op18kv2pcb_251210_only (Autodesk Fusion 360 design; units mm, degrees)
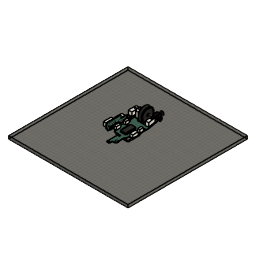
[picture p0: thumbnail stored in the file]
parameter "d441" = 0.2
place_component sketch "スケッチ1"
sketch "スケッチ1" plane through (0, 0, 0) normal (0, 0, 1) x axis (1, 0, 0)
  line L1 (-100, -100) -> (100, -100)
  line L2 (-100, 100) -> (-100, -100)
  line L3 (100, 100) -> (-100, 100)
  line L4 (100, -100) -> (100, 100)
  line L5 (-100, 100) -> (100, -100)
  line L6 (100, 100) -> (-100, -100)
  point P6 (0, 0)
  point P1 (0, 0)
  point P4 (-100, 100)
  point P5 (100, 100)
  point P3 (-100, -100)
  horizontal L1
  perpendicular L1 L2
  parallel L1 L3
  parallel L2 L4
  coincident L5 P6
  coincident L6 P6
  coincident P1 P6
  dimension "d13" distance P4 P5 = 200
  dimension "d14" distance P3 P4 = 200
extrude "押し出し1" new body sketch "スケッチ1" profile of L1 L2 L3 L4 against normal blind 5
sketch "スケッチ1" plane through (0, 0, 0) normal (0, 0, 1) x axis (1, 0, 0)
  line L1 (2, 0) -> (-2, 0)
  line L2 (2, -4) -> (2, 0)
  line L3 (-2, -4) -> (2, -4)
  line L4 (-2, 0) -> (-2, -4)
  line L5 (0, -7.68) -> (0, 0)
  line L6 (4.05, 8.27) -> (-4.05, 8.27)
  line L7 (4.05, -7.68) -> (4.05, 8.27)
  line L8 (-4.05, -7.68) -> (4.05, -7.68)
  line L9 (-4.05, 8.27) -> (-4.05, -7.68)
  arc A1 centre (0, 0) radius 2 clockwise from (-2, 0) to (2, 0)
  point P7 (0, -7.68)
  point P6 (0, 0)
  point P12 (0, 0)
  point P2 (-2, 0)
  point P3 (2, 0)
  point P5 (-2, -4)
  point P8 (-4.05, 8.27)
  point P9 (4.05, 8.27)
  point P11 (-4.05, -7.68)
  horizontal L1
  vertical L2
  horizontal L3
  vertical L4
  perpendicular L3 L5
  horizontal L6
  vertical L7
  horizontal L8
  vertical L9
  midpoint P7 L8
  coincident P6 P12
  dimension "d2" distance P2 P3 = 4
  dimension "d3" distance P2 P5 = 4
  dimension "d4" distance P6 P7 = 7.68
  dimension "d5" distance P8 P9 = 8.1
  dimension "d6" distance P8 P11 = 15.95
  dimension "d21" radius A1 = 2
extrude "押し出し2" new body sketch "スケッチ1" profile of L1 L2 L3 L4 L5 A1 along normal blind 2.4 taper 22.5 bodies "lens"
extrude "押し出し5" add sketch "スケッチ1" to an object from offset 7.4
sketch "スケッチ1" plane through (0, 0, 0) normal (0, 0, 1) x axis (1, 0, 0)
  line L1 (-10, -10) -> (10, -10)
  line L2 (-10, 10) -> (-10, -10)
  line L3 (10, 10) -> (-10, 10)
  line L4 (10, -10) -> (10, 10)
  line L5 (-10, 10) -> (10, -10)
  line L6 (10, 10) -> (-10, -10)
  line L7 (2, -4) -> (2, 0)
  line L8 (-2, -4) -> (2, -4)
  line L9 (-2, 0) -> (-2, -4)
  line L10 (3.5, -4.5) -> (3.5, 0)
  line L11 (-2.5, -5.5) -> (2.5, -5.5)
  line L12 (-3.5, 0) -> (-3.5, -4.5)
  line L13 (-6.5, 0) -> (-6.5, -4.5)
  line L14 (6.5, -4.5) -> (6.5, 0)
  line L15 (-2.5, -8.5) -> (2.5, -8.5)
  arc A1 centre (0, 0) radius 2 clockwise from (-2, 0) to (2, 0)
  arc A2 centre (0, 0) radius 3.5 clockwise from (-3.5, 0) to (3.5, 0)
  arc A3 centre (-2.5, -4.5) radius 1 clockwise from (-2.5, -5.5) to (-3.5, -4.5)
  arc A4 centre (2.5, -4.5) radius 1 clockwise from (3.5, -4.5) to (2.5, -5.5)
  arc A5 centre (0, 0) radius 6.5 clockwise from (-6.5, 0) to (6.5, 0)
  arc A6 centre (2.5, -4.5) radius 4 clockwise from (6.5, -4.5) to (2.5, -8.5)
  arc A7 centre (-2.5, -4.5) radius 4 clockwise from (-2.5, -8.5) to (-6.5, -4.5)
  point P6 (0, 0)
  point P1 (0, 0)
  point P7 (0, 0)
  point P4 (-10, 10)
  point P5 (10, 10)
  point P3 (-10, -10)
  point P9 (-2, 0)
  point P10 (2, 0)
  point P12 (-2, -4)
  horizontal L1
  perpendicular L1 L2
  parallel L1 L3
  parallel L2 L4
  coincident L5 P6
  coincident L6 P6
  coincident P1 P6
  coincident P1 P7
  vertical L7
  horizontal L8
  vertical L9
  concentric A1 A2
  tangent L12 A2
  tangent L12 A3
  tangent L11 A3
  tangent L10 A4
  tangent L11 A4
  equal A3 A4
  dimension "d29" distance P4 P5 = 20
  dimension "d30" distance P3 P4 = 20
  dimension "d40" radius A1 = 2
  dimension "d41" distance P9 P10 = 4
  dimension "d42" distance P9 P12 = 4
  dimension "d44" radius A3 = 1
  dimension "d45" = 3
extrude "押し出し2" sketch "スケッチ1" profile of L1 L2 L3 L4 A1 L7 L8 L9 L10 L11 L12 A2 A3 A4 L13 A7 L14 A5 A6 L15 to an object offset 0.5 from offset -0.5 bodies "around_lens"
extrude "押し出し3" cut sketch "スケッチ1" profile of L10 L11 L12 A2 A3 A4 L13 A7 L14 A5 A6 L15 along normal blind 0.7
combine "結合"
sketch "スケッチ1" plane through (0, 0, 0) normal (0, 0, 1) x axis (1, 0, 0)
  line L1 (0, -15) -> (0, 15)
  line L2 (-5.25, -15) -> (-5.25, 15)
  line L3 (5.25, -15) -> (5.25, 15)
  line L4 (-4.3, -15) -> (-4.3, 15)
  line L5 (4.3, -15) -> (4.3, 15)
  line L6 (10, 0) -> (-10, 0)
  line L7 (10, -8.44) -> (-10, -8.44)
  line L8 (10, 8.82) -> (-10, 8.82)
  line L9 (10, -5.66) -> (-10, -5.66)
  line L10 (10, 6.8) -> (-10, 6.8)
  line L11 (10, 7.69) -> (-10, 7.69)
  line L12 (10, -4.77) -> (-10, -4.77)
  line L13 (5.45, -15) -> (5.45, 15)
  line L14 (-5.45, -15) -> (-5.45, 15)
  line L15 (10, 7.94) -> (-10, 7.94)
  line L16 (10, 7.05) -> (-10, 7.05)
  line L17 (10, -5.02) -> (-10, -5.02)
  line L18 (10, -5.91) -> (-10, -5.91)
  point P1 (0, 0)
  vertical L1
  midpoint P1 L1
  perpendicular L2 L6
  midpoint P1 L6
  dimension "d91" = 5.25
  dimension "d92" = -5.25
  dimension "d93" = 4.3
  dimension "d94" = -4.3
  dimension "d95" = 8.44
  dimension "d96" = -8.82
  dimension "d97" = 5.66
  dimension "d102" = -12.46 (= "( -1.78 * 7 ) * 1 mm")
  dimension "d103" = -0.89
  dimension "d104" = -0.89
  dimension "d105" = -0.2
  dimension "d106" = 0.2
  dimension "d107" = -0.25
  dimension "d108" = -0.25
  dimension "d109" = 0.25
  dimension "d110" = 0.25
extrude "押し出し1" new body sketch "スケッチ1" profile of L1 L4 L5 L6 L7 L8 L9 L10 L11 L12 L15 L16 L17 L18 to an object offset 7.4 from offset 9.81 bodies "sensor"
extrude "押し出し2" sketch "スケッチ1" profile of L2 L3 L4 L5 L6 L9 L10 L11 L12 L13 L14 L15 L16 L17 L18 blind -0.2 from offset -0.5
extrude "押し出し3" sketch "スケッチ1" profile of L2 L3 L6 L9 L10 L11 L12 L13 L14 L15 L16 L17 L18 blind -4.51 from offset -0.5
sketch "スケッチ1" plane through (0, 0, 0) normal (0, 0, 1) x axis (1, 0, 0)
  line L1 (0, 15.4) -> (0, 0)
  line L2 (0, -14.4) -> (0, 0)
  line L3 (-4.3, 0) -> (4.3, 0)
  line L4 (-4.3, 8.82) -> (4.3, 8.82)
  line L5 (-4.3, -8.44) -> (4.3, -8.44)
  line L6 (4.3, 8.82) -> (4.3, -8.44)
  line L7 (-4.3, 8.82) -> (-4.3, -8.44)
  line L8 (12, 15.4) -> (0, 15.4)
  line L9 (-12.8, 15.4) -> (0, 15.4)
  line L10 (0, -31.8) -> (0, 0)
  circle C1 centre (12, 15.4) radius 1.4
  circle C2 centre (-12.8, 15.4) radius 1.4
  circle C3 centre (0, -14.4) radius 1.4
  circle C4 centre (0, -31.8) radius 1.4
  point P1 (0, 0)
  point P2 (0, 0)
  point P6 (0, 0)
  point P7 (0, -14.4)
  point P8 (0, -14.4)
  point P4 (12, 15.4)
  point P16 (12, 15.4)
  point P5 (-12.8, 15.4)
  point P17 (-12.8, 15.4)
  point P18 (0, 0)
  point P9 (0, -31.8)
  point P19 (0, -31.8)
  point P3 (0, 15.4)
  point P10 (4.3, 0)
  point P11 (-4.3, 0)
  coincident P1 P2
  vertical L1
  coincident P1 P6
  coincident P7 P8
  perpendicular L2 L3
  midpoint P6 L3
  perpendicular L4 L6
  perpendicular L4 L7
  perpendicular L1 L8
  perpendicular L1 L9
  coincident P4 P16
  coincident P5 P17
  coincident P1 P18
  perpendicular L3 L10
  coincident P9 P19
  dimension "d51" distance P2 P3 = 15.4
  dimension "d53" diameter C1 = 2.8
  dimension "d54" diameter C2 = 2.8
  dimension "d56" distance P6 P7 = 14.4
  dimension "d57" diameter C3 = 2.8
  dimension "d58" diameter C4 = 2.8
  dimension "d120" distance P10 P11 = 8.6
  dimension "d121" = 8.82
  dimension "d122" = -8.44
  dimension "d187" distance P3 P16 = 12
  dimension "d188" distance P3 P17 = 12.8
  dimension "d189" distance P18 P19 = 31.8
sketch "スケッチ2" plane through (0, 0, 0) normal (0, 0, 1) x axis (1, 0, 0)
  line L1 (50, 0) -> (-50, 0)
  line L2 (0, -50) -> (0, 50)
  line L3 (-13.8, -50) -> (-13.8, 50)
  line L4 (14, -50) -> (14, 50)
  line L5 (50, 39.3) -> (-50, 39.3)
  line L6 (50, -12.8) -> (-50, -12.8)
  line L7 (50, -33.6) -> (-50, -33.6)
  line L8 (-2.3, -50) -> (-2.3, 50)
  line L9 (2.3, -50) -> (2.3, 50)
  line L10 (7.3, -50) -> (7.3, 50)
  line L11 (50, -28.4) -> (-50, -28.4)
  line L12 (50, -9.7) -> (-50, -9.7)
  line L13 (-10.1, -50) -> (-10.1, 50)
  line L14 (9.3, -50) -> (9.3, 50)
  line L15 (50, -7.7) -> (-50, -7.7)
  line L16 (50, 36.5) -> (-50, 36.5)
  line L17 (-7.3, 39.3) -> (-10.1, 36.5)
  line L18 (10.6, -50) -> (10.6, 50)
  line L19 (14, 20.0176) -> (10.6, 39.3)
  point P1 (0, 0)
  point P34 (-10.1, 36.5)
  point P35 (-7.3, 39.3)
  point P38 (10.6, 39.3)
  point P39 (14, 20.0176)
  horizontal L1
  midpoint P1 L1
  vertical L2
  midpoint P1 L2
  coincident L13 P34
  coincident L16 P34
  coincident L5 P35
  coincident L18 P38
  coincident L5 P38
  coincident L4 P39
  dimension "d73" = 13.8
  dimension "d74" = -14
  dimension "d75" = -39.3
  dimension "d76" = 12.8
  dimension "d77" = 20.8
  dimension "d78" = 2.3
  dimension "d79" = -2.3
  dimension "d80" = -5
  dimension "d81" = -5.2
  dimension "d82" = -3.1
  dimension "d83" = -3.7
  dimension "d205" = 4.7
  dimension "d206" = -5.1
  dimension "d211" = -36.5
  dimension "d212" angle L5 L17 = 45
  dimension "d214" = 3.4
  dimension "d416" angle L5 L19 = 80
sketch "スケッチ3" plane through (0, 0, 0) normal (0, 0, 1) x axis (1, 0, 0)
  line L1 (25, 0) -> (-25, 0)
  line L2 (25, 22.2) -> (-25, 22.2)
  line L3 (25, 37.6) -> (-25, 37.6)
  line L4 (0, 50.6) -> (0, 0)
  line L5 (6.8, 50.6) -> (6.8, 0.6)
  line L6 (-6.8, 50.6) -> (-6.8, 0.6)
  line L7 (25, 36) -> (-25, 36)
  line L8 (25, 34.2) -> (-25, 34.2)
  line L9 (25, 23.1) -> (-25, 23.1)
  line L10 (25, 24.9) -> (-25, 24.9)
  line L11 (7.6, 50.6) -> (7.6, 0.6)
  line L12 (-7.6, 50.6) -> (-7.6, 0.6)
  circle C1 centre (-4.8, 35.6) radius 2
  circle C2 centre (-5.3, 23.7) radius 1.5
  circle C3 centre (5.6, 35.6) radius 2
  circle C4 centre (4.8, 24.2) radius 2
  point P1 (0, 0)
  point P8 (0, 0)
  horizontal L1
  coincident P1 P8
  perpendicular L3 L4
  tangent L6 C1
  tangent L3 C1
  tangent L2 C2
  tangent L6 C2
  tangent L3 C3
  tangent L11 C3
  tangent L5 C4
  tangent L2 C4
  dimension "d156" = -22.2
  dimension "d157" = -15.4
  dimension "d158" = 6.8
  dimension "d159" = -6.8
  dimension "d169" = 1.6
  dimension "d170" = 1.8
  dimension "d171" = -0.9
  dimension "d172" = -1.8
  dimension "d174" = 0.8
  dimension "d175" radius C1 = 2
  dimension "d176" radius C2 = 1.5
  dimension "d177" = -0.8
  dimension "d178" radius C3 = 2
  dimension "d179" radius C4 = 2
extrude "押し出し1" new body sketch "スケッチ2" blind -0.8 from offset 7.4 bodies "main_pcb"
extrude "押し出し2" cut sketch "スケッチ1" profile of L1 C1 C2 L2 C3 C4 L3 L4 L5 L6 L7 to an object
extrude "押し出し3" sketch "スケッチ3" profile of L2 L3 L4 L5 L6 L7 L8 L9 L10 L11 C1 C2 L12 C3 C4 to an object
sketch "スケッチ5" plane through (0, 0, 0) normal (0, 0, 1) x axis (1, 0, 0)
  line L1 (-12.25, 0) -> (0, 0)
  line L2 (-12.25, -5.5) -> (-12.25, 0)
  line L3 (0, -5.5) -> (-12.25, -5.5)
  line L4 (0, 0) -> (0, -5.5)
  line L5 (-11.45, 0) -> (0, 0)
  line L6 (-11.45, 9.05) -> (-11.45, 0)
  line L7 (0, 9.05) -> (-11.45, 9.05)
  line L8 (0, 0) -> (0, 9.05)
  line L9 (10.7, 0) -> (0, 0)
  line L10 (10.7, -2.8) -> (10.7, 0)
  line L11 (0, -2.8) -> (10.7, -2.8)
  line L12 (0, 0) -> (0, -2.8)
  line L13 (12.2, 0) -> (0, 0)
  line L14 (12.2, 9.05) -> (12.2, 0)
  line L15 (0, 9.05) -> (12.2, 9.05)
  line L16 (0, 0) -> (0, 9.05)
  line L17 (-12.5, -7.75) -> (-12.5, -3.25)
  line L18 (-12, -3.25) -> (-12, -7.75)
  line L19 (-12.25, -7.75) -> (-12.25, -3.25)
  line L20 (10.45, -5.8) -> (10.45, 0.2)
  line L21 (10.95, 0.2) -> (10.95, -5.8)
  line L22 (10.7, -5.8) -> (10.7, 0.2)
  line L23 (11.95, 7.55) -> (11.95, 10.55)
  line L24 (12.45, 10.55) -> (12.45, 7.55)
  line L25 (12.2, 7.55) -> (12.2, 10.55)
  line L26 (-11.7, 7.55) -> (-11.7, 10.55)
  line L27 (-11.2, 10.55) -> (-11.2, 7.55)
  line L28 (-11.45, 7.55) -> (-11.45, 10.55)
  line L29 (-13.8, -9.25) -> (-10.2, -9.25)
  line L30 (-13.8, -1.75) -> (-13.8, -9.25)
  line L31 (-10.2, -1.75) -> (-13.8, -1.75)
  line L32 (-10.2, -9.25) -> (-10.2, -1.75)
  line L33 (-13.8, -1.75) -> (-10.2, -9.25)
  line L34 (-10.2, -1.75) -> (-13.8, -9.25)
  line L35 (-13.5, 6.05) -> (-9.9, 6.05)
  line L36 (-13.5, 12.05) -> (-13.5, 6.05)
  line L37 (-9.9, 12.05) -> (-13.5, 12.05)
  line L38 (-9.9, 6.05) -> (-9.9, 12.05)
  line L39 (-13.5, 12.05) -> (-9.9, 6.05)
  line L40 (-9.9, 12.05) -> (-13.5, 6.05)
  line L41 (10.15, 6.05) -> (13.75, 6.05)
  line L42 (10.15, 12.05) -> (10.15, 6.05)
  line L43 (13.75, 12.05) -> (10.15, 12.05)
  line L44 (13.75, 6.05) -> (13.75, 12.05)
  line L45 (10.15, 12.05) -> (13.75, 6.05)
  line L46 (13.75, 12.05) -> (10.15, 6.05)
  line L47 (15.45, 1.7) -> (10.45, 1.7)
  line L48 (15.45, -7.3) -> (15.45, 1.7)
  line L49 (10.45, -7.3) -> (15.45, -7.3)
  line L50 (10.45, 1.7) -> (10.45, -7.3)
  line L51 (-12.95, 0) -> (0, 0)
  line L52 (-12.95, 20.2) -> (-12.95, 0)
  line L53 (0, 20.2) -> (-12.95, 20.2)
  line L54 (0, 0) -> (0, 20.2)
  line L55 (-11.9, 19.15) -> (-14, 19.15)
  line L56 (-11.9, 21.25) -> (-11.9, 19.15)
  line L57 (-14, 21.25) -> (-11.9, 21.25)
  line L58 (-14, 19.15) -> (-14, 21.25)
  line L59 (-11.9, 21.25) -> (-14, 19.15)
  line L60 (-14, 21.25) -> (-11.9, 19.15)
  line L61 (5.35, 0) -> (0, 0)
  line L62 (5.35, -24.1) -> (5.35, 0)
  line L63 (0, -24.1) -> (5.35, -24.1)
  line L64 (0, 0) -> (0, -24.1)
  line L65 (3.65, -25.8) -> (7.05, -25.8)
  line L66 (3.65, -22.4) -> (3.65, -25.8)
  line L67 (7.05, -22.4) -> (3.65, -22.4)
  line L68 (7.05, -25.8) -> (7.05, -22.4)
  line L69 (3.65, -22.4) -> (7.05, -25.8)
  line L70 (7.05, -22.4) -> (3.65, -25.8)
  line L71 (5.263, 34.1334) -> (10.2639, 35.0265)
  line L72 (7.5133, 21.5328) -> (5.263, 34.1334)
  line L73 (12.5142, 22.4259) -> (7.5133, 21.5328)
  line L74 (10.2639, 35.0265) -> (12.5142, 22.4259)
  line L75 (7.5133, 21.5328) -> (10.2639, 35.0265)
  line L76 (12.5142, 22.4259) -> (5.263, 34.1334)
  line L77 (8.0065, 33.2824) -> (9.7707, 23.2768)
  line L78 (8.55, 30.2) -> (8.8886, 28.2796)
  line L79 (7.2262, 29.3573) -> (10.0822, 29.8609)
  line L80 (7.0178, 30.5391) -> (7.2262, 29.3573)
  line L81 (9.8738, 31.0427) -> (7.0178, 30.5391)
  line L82 (10.0822, 29.8609) -> (9.8738, 31.0427)
  line L83 (7.0178, 30.5391) -> (10.0822, 29.8609)
  line L84 (9.8738, 31.0427) -> (7.2262, 29.3573)
  line L85 (9.6519, 22.7989) -> (10.0458, 22.8684)
  line L86 (7.7314, 33.6909) -> (9.6519, 22.7989)
  line L87 (8.1253, 33.7603) -> (7.7314, 33.6909)
  line L88 (10.0458, 22.8684) -> (8.1253, 33.7603)
  line L89 (7.7314, 33.6909) -> (10.0458, 22.8684)
  line L90 (8.1253, 33.7603) -> (9.6519, 22.7989)
  line L91 (8.55, 0) -> (0, 0)
  line L92 (8.55, 30.2) -> (8.55, 0)
  line L93 (0, 30.2) -> (8.55, 30.2)
  line L94 (0, 0) -> (0, 30.2)
  arc A1 centre (-12.25, -7.75) radius 0.25 clockwise from (-12, -7.75) to (-12.5, -7.75)
  arc A2 centre (-12.25, -3.25) radius 0.25 clockwise from (-12.5, -3.25) to (-12, -3.25)
  arc A3 centre (10.7, -5.8) radius 0.25 clockwise from (10.95, -5.8) to (10.45, -5.8)
  arc A4 centre (10.7, 0.2) radius 0.25 clockwise from (10.45, 0.2) to (10.95, 0.2)
  arc A5 centre (12.2, 7.55) radius 0.25 clockwise from (12.45, 7.55) to (11.95, 7.55)
  arc A6 centre (12.2, 10.55) radius 0.25 clockwise from (11.95, 10.55) to (12.45, 10.55)
  arc A7 centre (-11.45, 7.55) radius 0.25 clockwise from (-11.2, 7.55) to (-11.7, 7.55)
  arc A8 centre (-11.45, 10.55) radius 0.25 clockwise from (-11.7, 10.55) to (-11.2, 10.55)
  circle C1 centre (5.35, -24.1) radius 0.85
  point P1 (0, 0)
  point P2 (0, 0)
  point P6 (0, 0)
  point P10 (0, 0)
  point P14 (0, 0)
  point P4 (-12.25, -5.5)
  point P24 (-12.25, -5.5)
  point P12 (10.7, -2.8)
  point P31 (10.7, -2.8)
  point P16 (12.2, 9.05)
  point P38 (12.2, 9.05)
  point P8 (-11.45, 9.05)
  point P45 (-11.45, 9.05)
  point P50 (-12, -5.5)
  point P55 (-11.7, 9.05)
  point P60 (11.95, 9.05)
  point P65 (0, 0)
  point P73 (-12.95, 20.2)
  point P67 (-12.95, 20.2)
  point P74 (0, 0)
  point P82 (5.35, -24.1)
  point P76 (5.35, -24.1)
  point P83 (5.35, -24.1)
  point P88 (8.8886, 28.2796)
  point P91 (8.8886, 28.2796)
  point P92 (8.8886, 28.2796)
  point P98 (8.55, 30.2)
  point P93 (8.55, 30.2)
  point P103 (8.8886, 28.2796)
  point P104 (0, 0)
  point P106 (8.55, 30.2)
  point P3 (-12.25, 0)
  point P5 (0, -5.5)
  point P7 (-11.45, 0)
  point P9 (0, 9.05)
  point P11 (10.7, 0)
  point P13 (0, -2.8)
  point P15 (12.2, 0)
  point P17 (0, 9.05)
  point P48 (-13.8, -1.75)
  point P49 (-10.2, -1.75)
  point P47 (-13.8, -9.25)
  point P53 (-13.5, 12.05)
  point P54 (-9.9, 12.05)
  point P52 (-13.5, 6.05)
  point P58 (10.15, 12.05)
  point P59 (13.75, 12.05)
  point P57 (10.15, 6.05)
  point P61 (10.45, 1.7)
  point P62 (15.45, 1.7)
  point P64 (10.45, -7.3)
  point P66 (-12.95, 0)
  point P68 (0, 20.2)
  point P71 (-11.9, 21.25)
  point P72 (-14, 21.25)
  point P70 (-11.9, 19.15)
  point P75 (5.35, 0)
  point P77 (0, -24.1)
  point P80 (3.65, -22.4)
  point P81 (7.05, -22.4)
  point P79 (3.65, -25.8)
  point P86 (7.5133, 21.5328)
  point P87 (12.5142, 22.4259)
  point P85 (5.263, 34.1334)
  point P90 (8.0065, 33.2824)
  point P96 (7.0178, 30.5391)
  point P97 (9.8738, 31.0427)
  point P95 (7.2262, 29.3573)
  point P101 (7.7314, 33.6909)
  point P102 (8.1253, 33.7603)
  point P100 (9.6519, 22.7989)
  point P105 (8.55, 0)
  point P107 (0, 30.2)
  horizontal L1
  vertical L2
  horizontal L3
  vertical L4
  coincident P1 P2
  horizontal L5
  vertical L6
  horizontal L7
  vertical L8
  coincident P1 P6
  horizontal L9
  vertical L10
  horizontal L11
  vertical L12
  coincident P1 P10
  horizontal L13
  vertical L14
  horizontal L15
  vertical L16
  coincident P1 P14
  tangent L17 A1
  tangent A1 L18
  parallel L17 L18
  tangent L18 A2
  tangent L17 A2
  perpendicular L3 L19
  coincident P4 P24
  midpoint L19 P24
  tangent L20 A3
  tangent A3 L21
  parallel L20 L21
  tangent L21 A4
  tangent L20 A4
  perpendicular L11 L22
  coincident P12 P31
  midpoint L22 P31
  tangent L23 A5
  tangent A5 L24
  parallel L23 L24
  tangent L24 A6
  tangent L23 A6
  perpendicular L15 L25
  coincident P16 P38
  midpoint L25 P38
  tangent L26 A7
  tangent A7 L27
  parallel L26 L27
  tangent L27 A8
  tangent L26 A8
  perpendicular L7 L28
  coincident P8 P45
  midpoint L28 P45
  horizontal L29
  perpendicular L29 L30
  parallel L29 L31
  parallel L30 L32
  coincident L33 P50
  coincident L34 P50
  horizontal L35
  perpendicular L35 L36
  parallel L35 L37
  parallel L36 L38
  coincident L39 P55
  coincident L40 P55
  midpoint L26 P55
  horizontal L41
  perpendicular L41 L42
  parallel L41 L43
  parallel L42 L44
  coincident L45 P60
  coincident L46 P60
  horizontal L47
  vertical L48
  horizontal L49
  vertical L50
  midpoint L20 L50
  midpoint L18 P50
  midpoint L23 P60
  horizontal L51
  vertical L52
  horizontal L53
  vertical L54
  coincident P1 P65
  horizontal L55
  perpendicular L55 L56
  parallel L55 L57
  parallel L56 L58
  coincident L59 P73
  coincident L60 P73
  coincident P67 P73
  horizontal L61
  vertical L62
  horizontal L63
  vertical L64
  coincident P1 P74
  horizontal L65
  perpendicular L65 L66
  parallel L65 L67
  parallel L66 L68
  coincident L69 P82
  coincident L70 P82
  coincident P76 P82
  coincident P82 P83
  perpendicular L71 L72
  parallel L71 L73
  parallel L72 L74
  coincident L75 P88
  coincident L76 P88
  coincident P88 P91
  midpoint L77 P91
  coincident P88 P92
  parallel L77 L78
  perpendicular L79 L80
  parallel L79 L81
  parallel L80 L82
  coincident L83 P98
  coincident L84 P98
  coincident P93 P98
  parallel L77 L82
  perpendicular L85 L86
  parallel L85 L87
  parallel L86 L88
  coincident L89 P103
  coincident L90 P103
  coincident P88 P103
  parallel L77 L88
  horizontal L91
  vertical L92
  horizontal L93
  vertical L94
  coincident P1 P104
  coincident P98 P106
  dimension "d218" distance P2 P3 = 12.25
  dimension "d219" distance P2 P5 = 5.5
  dimension "d220" distance P6 P7 = 11.45
  dimension "d221" distance P6 P9 = 9.05
  dimension "d222" distance P10 P11 = 10.7
  dimension "d223" distance P10 P13 = 2.8
  dimension "d224" distance P14 P15 = 12.2
  dimension "d225" distance P14 P17 = 9.05
  dimension "d226" diameter A1 = 0.5
  dimension "d227" diameter A3 = 0.5
  dimension "d228" diameter A5 = 0.5
  dimension "d229" diameter A7 = 0.5
  dimension "d230" distance P48 P49 = 3.6
  dimension "d231" distance P47 P48 = 7.5
  dimension "d232" distance P53 P54 = 3.6
  dimension "d233" distance P52 P53 = 6
  dimension "d234" distance P58 P59 = 3.6
  dimension "d235" distance P57 P58 = 6
  dimension "d236" distance P61 P62 = 5
  dimension "d237" distance P61 P64 = 9
  dimension "d255" distance P65 P66 = 12.95
  dimension "d256" distance P65 P68 = 20.2
  dimension "d257" distance P71 P72 = 2.1
  dimension "d258" distance P70 P71 = 2.1
  dimension "d259" distance P74 P75 = 5.35
  dimension "d260" distance P74 P77 = 24.1
  dimension "d261" distance P80 P81 = 3.4
  dimension "d262" distance P79 P80 = 3.4
  dimension "d266" diameter C1 = 1.7
  dimension "d276" distance P86 P87 = 5.08
  dimension "d277" distance P85 P86 = 12.8
  dimension "d280" distance P90 P91 = 5.08
  dimension "d294" distance P92 P93 = 1.95
  dimension "d295" distance P96 P97 = 2.9
  dimension "d296" distance P95 P96 = 1.2
  dimension "d337" distance P101 P102 = 0.4
  dimension "d338" distance P100 P101 = 11.06 (= "( 5.53 * 2 ) * 1 mm")
  dimension "d369" distance P104 P105 = 8.55
  dimension "d370" distance P104 P107 = 30.2
  dimension "d415" angle L77 L93 = 80
extrude "押し出し4" sketch "スケッチ5" profile of L2 L3 L6 L7 L9 L10 L11 L13 L14 L15 L17 A1 L18 A2 L20 A3 L21 A4 L23 A5 L24 A6 L26 A7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 blind 5 bodies "zh_rmb", "zh_usb", "zh_lmb", "zh_side"
extrude "押し出し5" sketch "スケッチ5" profile of L2 L3 L6 L7 L9 L10 L11 L13 L14 L15 L17 A1 L18 A2 L20 A3 L21 A4 L23 A5 L24 A6 L26 A7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 blind -3
extrude "押し出し6" sketch "スケッチ5" profile of L52 L53 L55 L56 L57 L58 L62 L63 L65 L66 L67 L68 blind -1 bodies "LED", "dpi_sw"
extrude "押し出し7" sketch "スケッチ5" profile of L62 L63 C1 blind -0.7
extrude "押し出し8" sketch "スケッチ5" profile of L78 L79 L81 L85 L86 L87 L88 blind -3.2 bodies "whl_sw"
extrude "押し出し9" sketch "スケッチ5" profile of L71 L72 L73 L74 L78 L79 L80 L81 L82 blind 6.5
extrude "押し出し10" sketch "スケッチ5" profile of L79 L80 L81 L82 blind 0.85
sketch "スケッチ6" plane through (0, 0, 0) normal (1, 0, 0) x axis (0, 1, 0)
  line L1 (30.2, 0) -> (0, 0)
  line L2 (30.2, 7.4) -> (30.2, 0)
  line L3 (0, 7.4) -> (30.2, 7.4)
  line L4 (0, 0) -> (0, 7.4)
  line L5 (27.2, 7.4) -> (33.2, 7.4)
  line L6 (27.2, 3.9) -> (27.2, 7.4)
  line L7 (33.2, 3.9) -> (27.2, 3.9)
  line L8 (33.2, 7.4) -> (33.2, 3.9)
  line L9 (30.15, 20) -> (30.25, 20)
  line L10 (25.3, 7.4) -> (25.3, 20)
  line L11 (35.1, 7.4) -> (25.3, 7.4)
  line L12 (35.1, 20) -> (35.1, 7.4)
  line L13 (24.3, 7.4) -> (25.3, 7.4)
  line L14 (24.3, 3.9) -> (24.3, 7.4)
  line L15 (25.3, 3.9) -> (24.3, 3.9)
  line L16 (25.3, 7.4) -> (25.3, 3.9)
  line L17 (24.3, 5.65) -> (25.3, 7.4)
  line L18 (24.3, 5.65) -> (25.3, 3.9)
  line L19 (24.8759, 5.65) -> (25.7341, 7.1519)
  line L20 (24.8759, 5.65) -> (25.7341, 4.1481)
  line L21 (25.3, 3.9) -> (25.7341, 4.1481)
  line L22 (25.7341, 7.4) -> (25.7341, 7.1519)
  line L23 (35.1, 3.9) -> (34.6659, 4.1481)
  line L24 (36.1, 5.65) -> (35.1, 3.9)
  line L25 (35.5241, 5.65) -> (34.6659, 7.1519)
  line L26 (35.5241, 5.65) -> (34.6659, 4.1481)
  line L27 (34.6659, 7.4) -> (34.6659, 7.1519)
  line L28 (36.1, 5.65) -> (35.1, 7.4)
  line L29 (30.2, 16.4) -> (30.2, 7.4)
  line L30 (30.2, 15.4012) -> (29.335, 15.9006)
  line L31 (31.065, 15.9006) -> (30.2, 15.4012)
  line L32 (31.065, 16.8994) -> (31.065, 15.9006)
  line L33 (30.2, 17.3988) -> (31.065, 16.8994)
  line L34 (29.335, 16.8994) -> (30.2, 17.3988)
  line L35 (29.335, 15.9006) -> (29.335, 16.8994)
  line L36 (30.2, 20) -> (30.2, 17.3988)
  line L37 (28.0851, 19.3489) -> (25.3, 17.3988)
  line L38 (32.3149, 19.3489) -> (35.1, 17.3988)
  arc A1 centre (30.15, 16.4) radius 3.6 clockwise from (28.0851, 19.3489) to (30.15, 20)
  arc A2 centre (30.25, 16.4) radius 3.6 clockwise from (30.25, 20) to (32.3149, 19.3489)
  point P1 (0, 0)
  point P2 (0, 0)
  point P17 (24.3, 5.65)
  point P4 (30.2, 7.4)
  point P21 (25.7341, 7.4)
  point P12 (25.3, 7.4)
  point P27 (35.1, 7.4)
  point P16 (25.3, 3.9)
  point P23 (35.1, 3.9)
  point P28 (36.1, 5.65)
  point P18 (25.7341, 7.1519)
  point P24 (34.6659, 7.1519)
  point P19 (24.8759, 5.65)
  point P26 (35.5241, 5.65)
  point P20 (25.7341, 4.1481)
  point P25 (34.6659, 4.1481)
  point P22 (34.6659, 7.4)
  point P29 (30.2, 16.4)
  point P36 (30.2, 16.4)
  point P38 (25.3, 17.3988)
  point P39 (35.1, 17.3988)
  point P37 (30.2, 20)
  point P11 (25.3, 20)
  point P10 (35.1, 20)
  point P3 (30.2, 0)
  point P5 (0, 7.4)
  point P6 (33.2, 7.4)
  point P7 (27.2, 7.4)
  point P9 (33.2, 3.9)
  point P13 (35.1, 7.4)
  point P14 (24.3, 7.4)
  horizontal L1
  vertical L2
  horizontal L3
  vertical L4
  coincident P1 P2
  horizontal L5
  vertical L6
  horizontal L7
  vertical L8
  horizontal L9
  vertical L10
  horizontal L11
  vertical L12
  horizontal L13
  vertical L14
  horizontal L15
  vertical L16
  midpoint L14 P17
  perpendicular L18 L21
  midpoint P4 L5
  midpoint P4 L11
  perpendicular L11 L22
  coincident L3 P21
  symmetric L2 P12 P27
  symmetric L2 P16 P23
  symmetric L2 P17 P28
  symmetric L2 P18 P24
  symmetric L2 P19 P26
  symmetric L2 P20 P25
  symmetric L2 P21 P22
  perpendicular L3 L29
  coincident P29 P36
  perpendicular L9 L36
  coincident L10 P38
  symmetric L2 P38 P39
  coincident L9 P37
  coincident P11 L9
  tangent L37 A1
  tangent L9 A1
  coincident P10 L9
  tangent L38 A2
  tangent L9 A2
  equal A1 A2
  dimension "d340" distance P2 P3 = 30.2
  dimension "d341" distance P2 P5 = 7.4
  dimension "d342" distance P6 P7 = 6
  dimension "d343" distance P6 P9 = 3.5
  dimension "d344" distance P10 P11 = 9.8
  dimension "d345" distance P10 P13 = 12.6
  dimension "d348" distance P12 P14 = 1
  dimension "d349" distance P12 P16 = 3.5
  dimension "d352" = -0.5
  dimension "d353" distance P4 P29 = 9
  dimension "d354" distance P36 L35 = 0.865 (= "( 1.73 / 2 ) * 1 mm")
  dimension "d356" radius A1 = 3.6
extrude "押し出し13" new body sketch "スケッチ6" profile of L3 L5 L9 L10 L11 L12 L29 L30 L31 L32 L33 L34 L35 L36 L37 L38 A1 A2 blind 3 second side blind 1.4 from offset -11 bodies "whl_ec"
extrude "押し出し14" sketch "スケッチ6" profile of L3 L11 L16 L17 L18 L19 L20 L21 L22 L23 L24 L25 L26 L27 L28 blind 2 from offset -3
extrude "押し出し15" sketch "スケッチ6" profile of L2 L3 L5 L6 L7 L8 L11 blind 0.3 from offset -1
sketch "スケッチ1" plane through (0, 0, 0) normal (1, 0, 0) x axis (0, 1, 0)
  line L1 (0, 30) -> (0, 0)
  line L2 (30.2, 30) -> (30.2, 0)
  line L3 (40, 0) -> (0, 0)
  line L4 (40, 7.4) -> (0, 7.4)
  line L5 (40, 16.4) -> (0, 16.4)
  line L6 (30.2, 15.4012) -> (29.335, 15.9006)
  line L7 (31.065, 15.9006) -> (30.2, 15.4012)
  line L8 (31.065, 16.8994) -> (31.065, 15.9006)
  line L9 (30.2, 17.3988) -> (31.065, 16.8994)
  line L10 (29.335, 16.8994) -> (30.2, 17.3988)
  line L11 (29.335, 15.9006) -> (29.335, 16.8994)
  circle C1 centre (30.2, 16.4) radius 8.25
  circle C2 centre (30.2, 16.4) radius 9.4
  circle C3 centre (30.2, 16.4) radius 2.15
  circle C4 centre (30.2, 16.4) radius 1.8
  circle C5 centre (30.2, 16.4) radius 1.075
  circle C6 centre (30.2, 16.4) radius 10.675
  point P1 (0, 0)
  point P2 (0, 0)
  point P6 (0, 0)
  point P12 (30.2, 16.4)
  point P16 (30.2, 16.4)
  point P23 (30.2, 16.4)
  point P3 (0, 30)
  point P7 (40, 0)
  coincident P1 P2
  vertical L1
  coincident P1 P6
  perpendicular L2 L3
  coincident L2 P12
  coincident L5 P12
  concentric C1 C2
  concentric C2 C3
  concentric C1 C4
  concentric C4 C5
  coincident P16 P23
  concentric C5 C6
  dimension "d371" distance P2 P3 = 30
  dimension "d372" = 30.2
  dimension "d373" distance P6 P7 = 40
  dimension "d374" = -7.4
  dimension "d375" = -9
  dimension "d376" diameter C1 = 16.5
  dimension "d377" diameter C2 = 18.8
  dimension "d378" diameter C3 = 4.3
  dimension "d379" diameter C4 = 3.6
  dimension "d380" diameter C5 = 2.15
  dimension "d381" distance P23 L11 = 0.865 (= "( 1.73 / 2 ) * 1 mm")
  dimension "d394" diameter C6 = 21.35
extrude "押し出し1" new body sketch "スケッチ1" profile of L2 L4 L5 C1 C2 C3 C4 C5 L6 L7 L8 L9 L10 L11 distance 6.8 bodies "wheel"
extrude "押し出し2" cut sketch "スケッチ1" profile of L2 L4 L5 C1 C2 distance 5
extrude "押し出し3" add sketch "スケッチ1" profile of L2 L5 C3 C4 C5 L6 L7 L8 L9 L10 L11 distance 8.15
extrude "押し出し4" add sketch "スケッチ1" profile of L2 L5 L6 L7 L8 L9 L10 L11 against normal blind 10.6
extrude "押し出し5" add sketch "スケッチ1" profile of L2 L5 C5 L6 L7 L8 L9 L10 L11 against normal blind 5.7
extrude "押し出し6" add sketch "スケッチ1" profile of L2 L5 C4 C5 L6 L7 L8 L9 L10 L11 along normal blind 10.4
extrude "押し出し7" new body sketch "スケッチ1" profile of L2 L4 L5 C1 C2 C6 distance 5 bodies "wheel_ring"
sketch "スケッチ1" plane through (0, 0, 0) normal (0, 0, 1) x axis (1, 0, 0)
  line L1 (-22.9, 36.4) -> (-17.1, 36.4)
  line L2 (-22.9, 23.6) -> (-22.9, 36.4)
  line L3 (-17.1, 23.6) -> (-22.9, 23.6)
  line L4 (-17.1, 36.4) -> (-17.1, 23.6)
  line L5 (-22.9, 23.6) -> (-17.1, 36.4)
  line L6 (-17.1, 23.6) -> (-22.9, 36.4)
  line L7 (-20.2, 24.47) -> (-19.8, 24.47)
  line L8 (-20.2, 35.53) -> (-20.2, 24.47)
  line L9 (-19.8, 35.53) -> (-20.2, 35.53)
  line L10 (-19.8, 24.47) -> (-19.8, 35.53)
  line L11 (-20.2, 35.53) -> (-19.8, 24.47)
  line L12 (-19.8, 35.53) -> (-20.2, 24.47)
  line L13 (-20, 31.95) -> (-20, 30)
  line L14 (-21.45, 32.55) -> (-18.55, 32.55)
  line L15 (-21.45, 31.35) -> (-21.45, 32.55)
  line L16 (-18.55, 31.35) -> (-21.45, 31.35)
  line L17 (-18.55, 32.55) -> (-18.55, 31.35)
  line L18 (-21.45, 31.35) -> (-18.55, 32.55)
  line L19 (-18.55, 31.35) -> (-21.45, 32.55)
  line L20 (-20, 15) -> (-20, 45)
  line L21 (-25, 30) -> (-15, 30)
  line L22 (-25, 39.1) -> (-15, 39.1)
  line L23 (-25, 20.9) -> (-15, 20.9)
  line L24 (-23.35, 15) -> (-23.35, 45)
  line L25 (-16.65, 15) -> (-16.65, 45)
  line L26 (-25, 42.6) -> (-15, 42.6)
  line L27 (-25, 15.2) -> (-15, 15.2)
  line L28 (-23.9, 15) -> (-23.9, 45)
  line L29 (-16.1, 15) -> (-16.1, 45)
  line L30 (-25, 16.6) -> (-15, 16.6)
  line L31 (-22.6, 15.2) -> (-17.4, 15.2)
  line L32 (-22.6, 18) -> (-22.6, 15.2)
  line L33 (-17.4, 18) -> (-22.6, 18)
  line L34 (-17.4, 15.2) -> (-17.4, 18)
  line L35 (-22.6, 18) -> (-17.4, 15.2)
  line L36 (-17.4, 18) -> (-22.6, 15.2)
  line L37 (-18.5, 16.35) -> (-21.5, 16.35)
  line L38 (-21.5, 16.85) -> (-18.5, 16.85)
  line L39 (-18.5, 16.6) -> (-21.5, 16.6)
  circle C1 centre (-20, 39.1) radius 2.325
  circle C2 centre (-20, 20.9) radius 2.325
  arc A1 centre (-18.5, 16.6) radius 0.25 clockwise from (-18.5, 16.85) to (-18.5, 16.35)
  arc A2 centre (-21.5, 16.6) radius 0.25 clockwise from (-21.5, 16.35) to (-21.5, 16.85)
  circle C3 centre (-20, 20.9) radius 3.9
  point P6 (-20, 30)
  point P11 (-20, 30)
  point P12 (-20, 30)
  point P18 (-20, 31.95)
  point P13 (-20, 31.95)
  point P19 (-20, 39.1)
  point P20 (-20, 20.9)
  point P47 (-20, 16.6)
  point P54 (-20, 16.6)
  point P4 (-22.9, 23.6)
  point P5 (-17.1, 23.6)
  point P3 (-22.9, 36.4)
  point P9 (-20.2, 35.53)
  point P10 (-19.8, 35.53)
  point P8 (-20.2, 24.47)
  point P16 (-21.45, 31.35)
  point P17 (-18.55, 31.35)
  point P15 (-21.45, 32.55)
  point P45 (-22.6, 18)
  point P46 (-17.4, 18)
  point P44 (-22.6, 15.2)
  horizontal L1
  perpendicular L1 L2
  parallel L1 L3
  parallel L2 L4
  coincident L5 P6
  coincident L6 P6
  horizontal L7
  perpendicular L7 L8
  parallel L7 L9
  parallel L8 L10
  coincident L11 P11
  coincident L12 P11
  coincident P6 P11
  coincident P11 P12
  perpendicular L1 L13
  horizontal L14
  perpendicular L14 L15
  parallel L14 L16
  parallel L15 L17
  coincident L18 P18
  coincident L19 P18
  coincident P13 P18
  perpendicular L16 L20
  midpoint P6 L20
  perpendicular L2 L21
  midpoint P11 L21
  coincident P19 L20
  coincident P19 L22
  coincident P20 L20
  coincident P20 L23
  horizontal L31
  perpendicular L31 L32
  parallel L31 L33
  parallel L32 L34
  coincident L35 P47
  coincident L36 P47
  midpoint L30 P47
  tangent L37 A1
  tangent A1 L38
  parallel L37 L38
  tangent L38 A2
  tangent L37 A2
  parallel L30 L39
  coincident P47 P54
  midpoint L39 P54
  concentric C2 C3
  tangent L29 C3
  dimension "d448" distance P4 P5 = 5.8
  dimension "d449" distance P3 P4 = 12.8
  dimension "d450" distance P9 P10 = 0.4
  dimension "d451" distance P8 P9 = 11.06
  dimension "d452" distance P12 P13 = 1.95
  dimension "d453" distance P16 P17 = 2.9
  dimension "d454" distance P15 P16 = 1.2
  dimension "d456" diameter C1 = 4.65
  dimension "d457" diameter C2 = 4.65
  dimension "d458" = 9.1
  dimension "d459" = -9.1
  dimension "d460" = 3.35
  dimension "d461" = -3.35
  dimension "d462" = 12.6
  dimension "d463" = -14.8
  dimension "d464" = 3.9
  dimension "d465" = -3.9
  dimension "d466" = -13.4
  dimension "d467" distance P45 P46 = 5.2
  dimension "d468" distance P44 P45 = 2.8
  dimension "d469" diameter A1 = 0.5
extrude "押し出し1" new body sketch "スケッチ1" profile of L1 L2 L3 L4 L7 L8 L9 L10 L13 L14 L15 L16 L17 C1 C2 L20 L21 L22 L23 L24 L25 L26 L27 L28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 blind -0.8 from offset 7.4 bodies "pcb"
extrude "押し出し2" sketch "スケッチ1" profile of L1 L2 L3 L4 L7 L8 L9 L10 L13 L14 L15 L16 L17 L20 L21 blind 6.5 bodies "switch"
extrude "押し出し3" sketch "スケッチ1" profile of L8 L10 L13 L14 L15 L16 L17 L20 blind 0.85
extrude "押し出し4" sketch "スケッチ1" profile of L7 L8 L9 L10 L13 L14 L16 L20 L21 blind -3.2
extrude "押し出し5" sketch "スケッチ1" profile of L20 L27 L30 L31 L32 L33 L34 L37 A1 L38 A2 blind -5 bodies "conn"
extrude "押し出し6" sketch "スケッチ1" profile of L20 L30 L37 A1 L38 A2 blind 2.5
sketch "スケッチ1" plane through (0, 0, 0) normal (1, 0, 0) x axis (0, 1, 0)
  line L1 (-25, 0) -> (25, 0)
  line L2 (-25, 7.4) -> (25, 7.4)
  line L3 (-25, 7.9) -> (25, 7.9)
  line L4 (-25, 19.8) -> (25, 19.8)
  line L5 (-25, 14.8) -> (25, 14.8)
  line L6 (0, 25) -> (0, 0)
  line L7 (-4.1, 25) -> (-4.1, 0)
  line L8 (13.2, 25) -> (13.2, 0)
  line L9 (14.3, 24.9) -> (14.3, -0.1)
  line L10 (4.3, 25) -> (4.3, 0)
  line L11 (-25, 10.9) -> (25, 10.9)
  line L12 (-20, 25) -> (-20, 0)
  line L13 (-17.6, 25) -> (-17.6, 0)
  line L14 (-20, 17.8) -> (-18, 19.8)
  line L15 (14.3, 12.8) -> (12.3, 14.8)
  line L16 (-25, 10.5) -> (25, 10.5)
  line L17 (-25, 11.8) -> (25, 11.8)
  point P1 (0, 0)
  point P12 (0, 0)
  point P28 (-18, 19.8)
  point P29 (-20, 17.8)
  point P30 (12.3, 14.8)
  point P31 (14.3, 12.8)
  horizontal L1
  coincident P1 P12
  perpendicular L4 L6
  coincident L4 P28
  coincident L12 P29
  coincident L5 P30
  coincident L9 P31
  dimension "d507" = 7.4
  dimension "d508" = 0.5
  dimension "d509" = 12.4
  dimension "d510" distance ORIGIN L2 = 7.4
  dimension "d511" = -4.1
  dimension "d512" = 13.2
  dimension "d513" = 14.3
  dimension "d514" = 4.3
  dimension "d515" = 3.5
  dimension "d516" = -20
  dimension "d517" = -17.6
  dimension "d523" distance L12 P28 = 2
  dimension "d524" distance L4 P29 = 2
  dimension "d525" distance L9 P30 = 2
  dimension "d526" distance L5 P31 = 2
  dimension "d527" = 3.1
  dimension "d528" = 4.4
extrude "押し出し1" new body sketch "スケッチ1" profile of L2 L3 L4 L5 L6 L7 L8 L9 L10 L11 L12 L13 L14 L15 L16 L17 blind -1.2 from offset -16 bodies "pcb"
sketch "スケッチ2" plane through (0, 0, 0) normal (1, 0, 0) x axis (0, 1, 0)
  line L1 (-25, 0) -> (25, 0)
  line L2 (0, 25) -> (0, 0)
  line L3 (-25.1, 7.4) -> (24.9, 7.4)
  line L4 (-25.1, 11) -> (24.9, 11)
  line L5 (6.8, 25) -> (6.8, 0)
  line L6 (13.2, 8.1) -> (0.4, 8.1)
  line L7 (13.2, 13.9) -> (13.2, 8.1)
  line L8 (0.4, 13.9) -> (13.2, 13.9)
  line L9 (0.4, 8.1) -> (0.4, 13.9)
  line L10 (13.2, 13.9) -> (0.4, 8.1)
  line L11 (0.4, 13.9) -> (13.2, 8.1)
  line L12 (12.33, 10.8) -> (1.27, 10.8)
  line L13 (12.33, 11.2) -> (12.33, 10.8)
  line L14 (1.27, 11.2) -> (12.33, 11.2)
  line L15 (1.27, 10.8) -> (1.27, 11.2)
  line L16 (12.33, 11.2) -> (1.27, 10.8)
  line L17 (1.27, 11.2) -> (12.33, 10.8)
  line L18 (8.75, 11) -> (6.8, 11)
  line L19 (9.35, 9.55) -> (8.15, 9.55)
  line L20 (9.35, 12.45) -> (9.35, 9.55)
  line L21 (8.15, 12.45) -> (9.35, 12.45)
  line L22 (8.15, 9.55) -> (8.15, 12.45)
  line L23 (9.35, 12.45) -> (8.15, 9.55)
  line L24 (8.15, 12.45) -> (9.35, 9.55)
  line L25 (-5.57, 14.5) -> (-16.63, 14.1)
  line L26 (-16.63, 14.1) -> (-16.63, 14.5)
  line L27 (-9.75, 15.75) -> (-8.55, 12.85)
  line L28 (-16.63, 14.5) -> (-5.57, 14.5)
  line L29 (-9.75, 15.75) -> (-8.55, 15.75)
  line L30 (-9.75, 12.85) -> (-9.75, 15.75)
  line L31 (-17.5, 17.2) -> (-4.7, 17.2)
  line L32 (-4.7, 17.2) -> (-4.7, 11.4)
  line L33 (-8.55, 15.75) -> (-8.55, 12.85)
  line L34 (-8.55, 15.75) -> (-9.75, 12.85)
  line L35 (-17.5, 17.2) -> (-4.7, 11.4)
  line L36 (-9.15, 14.3) -> (-11.1, 14.3)
  line L37 (-8.55, 12.85) -> (-9.75, 12.85)
  line L38 (-5.57, 14.1) -> (-16.63, 14.1)
  line L39 (-5.57, 14.5) -> (-5.57, 14.1)
  line L40 (-16.63, 14.5) -> (-5.57, 14.1)
  line L41 (-4.7, 17.2) -> (-17.5, 11.4)
  line L42 (-17.5, 11.4) -> (-17.5, 17.2)
  line L43 (-4.7, 11.4) -> (-17.5, 11.4)
  line L44 (-25.1, 14.3) -> (24.9, 14.3)
  line L45 (-11.1, 25) -> (-11.1, 0)
  line L46 (-25.1, 9) -> (24.9, 9)
  line L47 (-7.6, 8) -> (-14.6, 8)
  line L48 (-7.6, 10) -> (-7.6, 8)
  line L49 (-14.6, 10) -> (-7.6, 10)
  line L50 (-14.6, 8) -> (-14.6, 10)
  line L51 (-7.6, 10) -> (-14.6, 8)
  line L52 (-14.6, 10) -> (-7.6, 8)
  point P1 (0, 0)
  point P4 (0, 0)
  point P16 (6.8, 11)
  point P21 (6.8, 11)
  point P22 (6.8, 11)
  point P28 (8.75, 11)
  point P23 (8.75, 11)
  point P43 (-11.1, 14.3)
  point P45 (-11.1, 14.3)
  point P44 (-11.1, 14.3)
  point P42 (-9.15, 14.3)
  point P35 (-9.15, 14.3)
  point P56 (-11.1, 9)
  point P14 (13.2, 13.9)
  point P15 (0.4, 13.9)
  point P13 (13.2, 8.1)
  point P19 (12.33, 11.2)
  point P20 (1.27, 11.2)
  point P18 (12.33, 10.8)
  point P26 (9.35, 12.45)
  point P27 (8.15, 12.45)
  point P25 (9.35, 9.55)
  point P38 (-4.7, 17.2)
  point P39 (-17.5, 17.2)
  point P37 (-4.7, 11.4)
  point P29 (-5.57, 14.5)
  point P30 (-16.63, 14.5)
  point P32 (-5.57, 14.1)
  point P40 (-9.75, 15.75)
  point P41 (-8.55, 15.75)
  point P33 (-8.55, 12.85)
  point P54 (-7.6, 10)
  point P55 (-14.6, 10)
  point P53 (-7.6, 8)
  horizontal L1
  coincident P1 P4
  perpendicular L1 L2
  horizontal L6
  perpendicular L6 L7
  parallel L6 L8
  parallel L7 L9
  coincident L10 P16
  coincident L11 P16
  horizontal L12
  perpendicular L12 L13
  parallel L12 L14
  parallel L13 L15
  coincident L16 P21
  coincident L17 P21
  coincident P16 P21
  coincident P21 P22
  perpendicular L7 L18
  horizontal L19
  perpendicular L19 L20
  parallel L19 L21
  parallel L20 L22
  coincident L23 P28
  coincident L24 P28
  coincident P23 P28
  horizontal L43
  perpendicular L32 L43
  parallel L31 L43
  parallel L32 L42
  coincident P43 L41
  coincident P43 L35
  horizontal L38
  perpendicular L38 L39
  parallel L28 L38
  parallel L26 L39
  coincident P45 L25
  coincident P45 L40
  coincident P43 P45
  coincident P44 P45
  perpendicular L32 L36
  horizontal L37
  perpendicular L33 L37
  parallel L29 L37
  parallel L30 L33
  coincident P42 L34
  coincident P42 L27
  coincident P35 P42
  coincident L4 P16
  coincident L5 P16
  coincident P45 L45
  coincident P43 L44
  horizontal L47
  perpendicular L47 L48
  parallel L47 L49
  parallel L48 L50
  coincident L51 P56
  coincident L52 P56
  coincident L45 P56
  coincident L46 P56
  dimension "d537" = 7.4
  dimension "d538" = 3.6
  dimension "d539" = 6.8
  dimension "d540" distance P14 P15 = 12.8
  dimension "d541" distance P13 P14 = 5.8
  dimension "d542" distance P19 P20 = 11.06
  dimension "d543" distance P18 P19 = 0.4
  dimension "d544" distance P22 P23 = 1.95
  dimension "d545" distance P26 P27 = 1.2
  dimension "d546" distance P25 P26 = 2.9
  dimension "d547" distance P38 P39 = 12.8
  dimension "d548" distance P37 P38 = 5.8
  dimension "d549" distance P29 P30 = 11.06
  dimension "d550" distance P29 P32 = 0.4
  dimension "d551" distance P35 P44 = 1.95
  dimension "d552" distance P40 P41 = 1.2
  dimension "d553" distance P33 P41 = 2.9
  dimension "d554" = 6.9
  dimension "d555" = -11.1
  dimension "d556" = 1.6
  dimension "d557" distance P54 P55 = 7
  dimension "d558" distance P53 P54 = 2
extrude "押し出し3" sketch "スケッチ2" profile of L4 L5 L6 L7 L8 L9 L12 L13 L14 L15 L18 L19 L20 L21 L22 L26 L28 L29 L30 L31 L32 L33 L36 L37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 blind -6.5 bodies "switch5", "switch4"
extrude "押し出し4" sketch "スケッチ2" profile of L4 L12 L14 L18 L19 L20 L21 L22 L28 L29 L30 L33 L36 L37 L38 L44 blind -0.85
extrude "押し出し5" sketch "スケッチ2" profile of L4 L5 L12 L13 L14 L15 L18 L20 L22 L26 L28 L30 L33 L36 L38 L39 L44 L45 blind 3.2
extrude "押し出し6" sketch "スケッチ2" profile of L45 L46 L47 L48 L49 L50 blind 2.4 second side blind 1.2
sketch "スケッチ1" plane through (0, 0, 0) normal (0, 1, 0) x axis (1, 0, 0)
  line L1 (-10, 0) -> (10, 0)
  line L2 (-10, -7.4) -> (10, -7.4)
  line L3 (0, -15) -> (0, 0)
  line L4 (-10, -0.9) -> (10, -0.9)
  line L5 (-10, -4.9) -> (10, -4.9)
  line L6 (-4.9, -15) -> (-4.9, 0)
  line L7 (4.9, -15) -> (4.9, 0)
  line L8 (-2.5, -15) -> (-2.5, 0)
  line L9 (2.5, -15) -> (2.5, 0)
  line L10 (-7.4, -15) -> (-7.4, 0)
  line L11 (7.4, -15) -> (7.4, 0)
  circle C1 centre (0, -4.15) radius 3.25
  circle C2 centre (0, -4.15) radius 1.25
  point P1 (0, 0)
  point P6 (0, 0)
  horizontal L1
  coincident P1 P6
  perpendicular L2 L3
  tangent L4 C1
  concentric C1 C2
  dimension "d582" = -7.4
  dimension "d583" = 6.5
  dimension "d584" = -4
  dimension "d585" = 4.9
  dimension "d586" = -4.9
  dimension "d587" = 2.5
  dimension "d588" = -2.5
  dimension "d595" = 7.4
  dimension "d596" = -7.4
  dimension "d600" diameter C2 = 2.5
extrude "押し出し1" new body sketch "スケッチ1" profile of L2 L3 L4 L5 L6 L7 L8 L9 C1 L10 L11 C2 blind 6 from offset 46 bodies "bush"
extrude "押し出し2" sketch "スケッチ1" profile of L2 L3 L4 L5 L8 L9 C1 blind -1.5
extrude "押し出し3" sketch "スケッチ1" profile of L2 L3 L4 L5 L6 L7 L8 L9 C1 blind -2
extrude "押し出し4" sketch "スケッチ1" profile of L3 L5 C2 blind -2.5
extrude "押し出し5" sketch "スケッチ1" profile of L3 L5 L8 L9 C1 C2 blind 5
chamfer "面取り" distance 6.5 Rotate Angle 30
fillet "フィレット" radius 2.4 1
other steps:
create_component "CreateComponent1"
create_component "CreateComponent2" sketch "スケッチ1"
create_component "CreateComponent3"
create_component "CreateComponent4"
create_component "CreateComponent5"
create_component "CreateComponent7"
create_component "CreateComponent8"
create_component "CreateComponent9"
create_component "CreateComponent10"
named bodies: "lens", "around_lens", "main_pcb", "sensor", "zh_rmb", "zh_usb", "zh_lmb", "zh_side", "LED", "dpi_sw", "whl_sw", "whl_ec", "wheel", "wheel_ring", "switch", "conn", "pcb", "switch5", "switch4", "bush"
